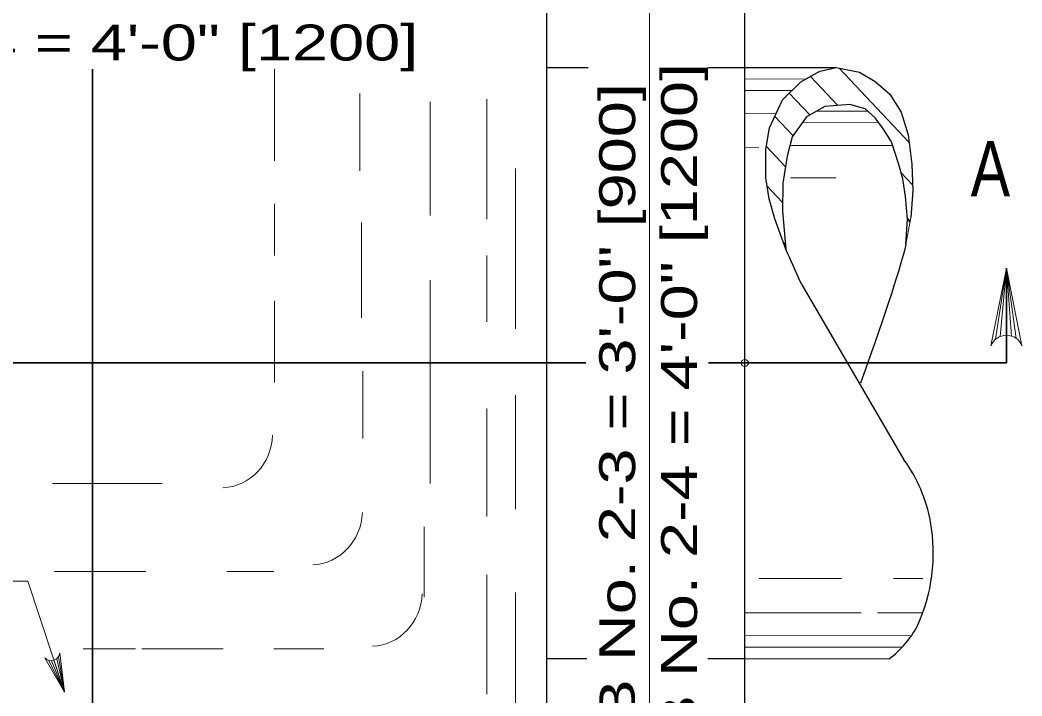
# Model space of a CAD drawing. Extents: x 1083.1 to 1117.1, y 697.4 to 719.4.
# Drawn here: x 1103.719 to 1108.069, y 701.901 to 704.837 of the extents above; entities that cross this region are included whole.
import ezdxf

# ---------------------------------------------------------------- set-up
doc = ezdxf.new("R2010")
doc.units = 0
doc.header["$LTSCALE"] = 0.062
doc.header["$PDMODE"] = 32
doc.header["$PDSIZE"] = 0.031
doc.linetypes.add('LONG_DASHED', pattern=[7.5, 6, -1.5])
doc.layers.add('1', color=7, linetype='Continuous', lineweight=13)

msp = doc.modelspace()

# ---------------------------------------------------------------- linework, layer by layer
at = {"layer": '1', "lineweight": 25}
for p, q in [((1106.86575, 701.19417), (1106.86575, 705.43083)), ((1106.00575, 701.25917), (1106.00575, 705.36217)), ((1106.86758, 704.6305), (1107.26308, 704.62983)), ((1107.193, 704.61425), (1107.26308, 704.62983)), ((1107.11225, 703.69033), (1107.55675, 702.92742)), ((1106.86383, 702.06425), (1107.4925, 702.06325))]:
    msp.add_line(p, q, dxfattribs=at)
at = {"layer": '1'}
for p, q in [((1106.45208, 705.36217), (1106.45208, 701.25917)), ((1104.82342, 704.22467), (1104.82342, 704.62475)), ((1107.26308, 704.62983), (1107.36308, 704.6105)), ((1107.27608, 704.62717), (1107.58, 704.30458)), ((1106.86742, 704.58075), (1107.13208, 704.58033)), ((1107.03008, 704.49058), (1107.10725, 704.5665)), ((1107.15117, 704.59092), (1107.2695, 704.46533)), ((1105.19492, 704.51742), (1105.19492, 704.1825)), ((1106.86742, 704.53117), (1107.071, 704.53075)), ((1107.05908, 704.51925), (1107.14858, 704.42433)), ((1105.50008, 704.48092), (1105.50008, 703.98758)), ((1105.74617, 703.97258), (1105.74617, 704.49233)), ((1106.86733, 704.43167), (1107.00267, 704.4315)), ((1107.17783, 704.44083), (1107.39917, 704.4405)), ((1106.99625, 704.41758), (1107.07533, 704.33367)), ((1107.11608, 704.39125), (1107.44758, 704.39067)), ((1106.867, 704.28258), (1106.92725, 704.28242)), ((1106.95967, 704.28733), (1107.04258, 704.19942)), ((1107.062, 704.29192), (1107.50833, 704.29125)), ((1105.86958, 703.49642), (1105.86958, 704.1925)), ((1107.54475, 704.17292), (1107.594, 704.12075)), ((1107.06458, 704.15108), (1107.26142, 704.15075)), ((1106.96333, 704.11483), (1107.02992, 704.04392)), ((1104.82342, 703.81433), (1104.82342, 704.03792)), ((1105.20142, 703.95708), (1105.20142, 703.543)), ((1107.58725, 703.97925), (1107.56567, 703.8615)), ((1107.58725, 703.97925), (1107.56567, 703.8615)), ((1107.57167, 703.97558), (1107.58425, 703.96233)), ((1107.57183, 703.9705), (1107.58342, 703.95808)), ((1107.56808, 703.904), (1107.57267, 703.89925)), ((1107.03433, 703.87033), (1107.04267, 703.86125)), ((1107.04192, 703.84925), (1107.04417, 703.847)), ((1105.74617, 703.52567), (1105.74617, 703.81383)), ((1107.95475, 703.45042), (1108.00183, 703.75858)), ((1107.9745, 703.46208), (1108.00183, 703.75858)), ((1108.00183, 703.4675), (1108.00183, 703.75858)), ((1108.02342, 703.46433), (1108.00183, 703.75858)), ((1108.0445, 703.454), (1108.00183, 703.75858)), ((1105.50008, 703.70742), (1105.50008, 702.82433)), ((1104.82342, 703.26308), (1104.82342, 703.6175)), ((1105.20792, 703.3115), (1105.20792, 703.01917)), ((1105.86958, 702.713), (1105.86958, 703.20708)), ((1105.74617, 702.68142), (1105.74617, 703.14942)), ((1103.85917, 702.82433), (1104.33525, 702.82433)), ((1105.47417, 702.6355), (1105.47417, 702.331)), ((1103.868, 702.44158), (1104.26475, 702.44158)), ((1104.61742, 702.44158), (1104.82025, 702.44158)), ((1105.74617, 701.9095), (1105.74617, 702.42767)), ((1103.75192, 702.40033), (1103.475, 702.40033)), ((1103.91208, 701.91825), (1103.75192, 702.40033)), ((1106.92867, 702.41192), (1107.28633, 702.4115)), ((1107.51158, 702.41117), (1107.63842, 702.411)), ((1105.86958, 701.71342), (1105.86958, 702.35083)), ((1106.86425, 702.26308), (1107.37125, 702.26217)), ((1107.44125, 702.26217), (1107.63825, 702.26183)), ((1106.864, 702.16367), (1107.58875, 702.16242)), ((1103.993, 702.1055), (1104.22058, 702.1055)), ((1104.24708, 702.1055), (1104.60075, 702.1055)), ((1104.82025, 702.1055), (1105.03792, 702.1055)), ((1106.864, 702.11392), (1107.5485, 702.11275)), ((1103.84383, 702.05608), (1103.91208, 701.91825)), ((1103.8555, 702.0545), (1103.91208, 701.91825)), ((1103.86617, 702.05642), (1103.91208, 701.91825)), ((1103.87833, 702.06325), (1103.91208, 701.91825)), ((1103.88583, 702.07192), (1103.91208, 701.91825))]:
    msp.add_line(p, q, dxfattribs=at)
at = {"layer": '1', "lineweight": 35}
for p, q in [((1104.03408, 699.48033), (1104.03408, 704.62275)), ((1108.00183, 703.75858), (1108.00183, 703.34742)), ((1100.08533, 703.34742), (1104.89842, 703.34742)), ((1104.89842, 703.34742), (1106.1755, 703.34742)), ((1106.70792, 703.34742), (1108.00183, 703.34742))]:
    msp.add_line(p, q, dxfattribs=at)
at = {"layer": '1', "linetype": 'LONG_DASHED', "lineweight": 25}
for p, q in [((1106.00575, 704.6305), (1106.18583, 704.6305)), ((1106.70533, 704.6305), (1106.86758, 704.6305)), ((1106.00575, 702.06425), (1106.17933, 702.06425)), ((1106.70533, 702.06425), (1106.86383, 702.06425))]:
    msp.add_line(p, q, dxfattribs=at)
at = {"layer": '1', "lineweight": 25}
for points in [[(1107.04442, 703.84225), (1106.99625, 703.97392), (1106.97217, 704.05975), (1106.95692, 704.15167), (1106.95758, 704.27492), (1106.97342, 704.36875), (1107.03008, 704.49058), (1107.10942, 704.56875), (1107.19125, 704.61425)], [(1107.193, 704.61425), (1107.26308, 704.62983), (1107.36308, 704.6105), (1107.43208, 704.56983), (1107.49592, 704.51425), (1107.54417, 704.43633), (1107.57583, 704.33792), (1107.59167, 704.21058), (1107.59483, 704.09617), (1107.58725, 703.97925)], [(1107.36308, 704.6105), (1107.43208, 704.56983), (1107.49592, 704.51425), (1107.54417, 704.43633), (1107.57583, 704.33792), (1107.59167, 704.21058), (1107.59483, 704.09617), (1107.58725, 703.97925)], [(1106.97217, 704.05975), (1106.95692, 704.15167), (1106.95758, 704.27492), (1106.97342, 704.36875), (1107.03008, 704.49058)], [(1107.56567, 703.8615), (1107.572, 703.9725), (1107.56292, 704.071), (1107.55192, 704.1465), (1107.53375, 704.21433), (1107.50292, 704.30717), (1107.46817, 704.36325), (1107.43192, 704.41175), (1107.388, 704.45042), (1107.32217, 704.47), (1107.21267, 704.4605), (1107.13392, 704.416), (1107.07183, 704.32917), (1107.04967, 704.246), (1107.03133, 704.128), (1107.02925, 704.00608), (1107.04442, 703.84225)], [(1107.56567, 703.8615), (1107.572, 703.9725), (1107.56292, 704.071), (1107.55192, 704.1465), (1107.53375, 704.21433), (1107.50292, 704.30717), (1107.46817, 704.36325), (1107.43192, 704.41175), (1107.388, 704.45042), (1107.32217, 704.47), (1107.21267, 704.4605), (1107.13392, 704.416), (1107.07183, 704.32917), (1107.04967, 704.246), (1107.03133, 704.128), (1107.02925, 704.00608), (1107.04442, 703.84225)]]:
    msp.add_lwpolyline(points, dxfattribs=at)
at = {"layer": '1'}
for points in [[(1107.04442, 703.84225), (1106.99625, 703.97392), (1106.97217, 704.05975)], [(1107.93458, 703.42217), (1108.00183, 703.75858), (1108.06917, 703.42217)], [(1103.891, 702.0885), (1103.91208, 701.91825), (1103.82708, 702.06733)]]:
    msp.add_lwpolyline(points, dxfattribs=at)
for centre, radius, start, end in [((1108.00194, 703.395), 0.07261, 22.08782, 157.91395), ((1103.85472, 702.09079), 0.03631, 220.4653, 356.29143)]:
    msp.add_arc(centre, radius, start, end, dxfattribs=at)
for centre in [(1104.59153, 703.04297), (1104.98116, 702.708), (1105.24091, 702.35476)]:
    msp.add_ellipse(centre, major_axis=(0, 0.23746), ratio=0.944544, start_param=3.178636, end_param=4.6723832, dxfattribs=at)
at = {"layer": '1', "lineweight": 25}
for centre, major_axis, start_param, end_param in [((1107.07287, 702.53287), (0, 0.6467), 4.9058986, 5.3686347), ((1107.00837, 702.52181), (0, 0.71577), 4.251341, 4.9027182), ((1107.25987, 702.41793), (0, -0.43184), 0.6070417, 1.0508543)]:
    msp.add_ellipse(centre, major_axis=major_axis, ratio=0.944544, start_param=start_param, end_param=end_param, dxfattribs=at)
for points in [[(1107.56567, 703.8615), (1107.5405, 703.75908), (1107.48767, 703.5945), (1107.36825, 703.26025)], [(1107.11225, 703.69033), (1107.08558, 703.74633), (1107.06325, 703.79683), (1107.04442, 703.84225)]]:
    msp.add_open_spline(points, degree=3, dxfattribs=at)
at = {"layer": '1'}
msp.add_point((1106.86575, 703.34742), dxfattribs=at)

# ---------------------------------------------------------------- texts
for s, height, width, p in [('CB No. 2-4 = 4\'-0" [1200]', 0.156, 1.35, (1102.31192, 704.661)), ('A', 0.24, 0.8, (1107.84642, 704.07067))]:
    msp.add_text(s, height=height, dxfattribs=dict(at, width=width)).set_placement(p)
at = {"layer": '1', "width": 1.35}
for s, p in [('CB No. 2-4 = 4\'-0" [1200]', (1106.65833, 701.51433)), ('CB No. 2-3 = 3\'-0" [900]', (1106.38967, 701.58333))]:
    msp.add_text(s, height=0.156, rotation=90, dxfattribs=at).set_placement(p)

doc.saveas('drawing.dxf')
